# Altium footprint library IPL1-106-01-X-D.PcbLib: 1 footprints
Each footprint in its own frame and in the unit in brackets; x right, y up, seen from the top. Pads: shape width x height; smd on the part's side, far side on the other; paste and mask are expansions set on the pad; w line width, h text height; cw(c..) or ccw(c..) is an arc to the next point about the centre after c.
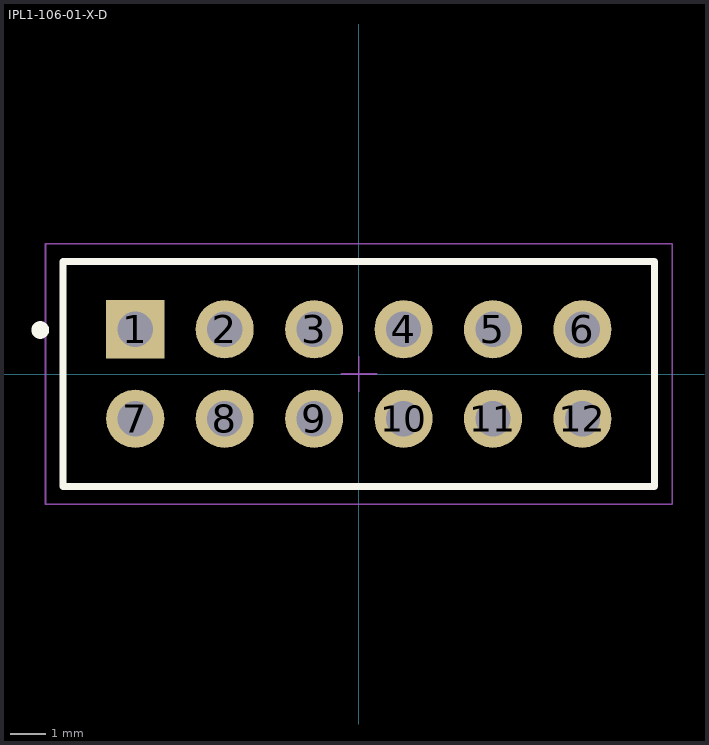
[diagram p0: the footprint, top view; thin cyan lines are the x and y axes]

## IPL1-106-01-X-D [mm] "2.54mm pitch, 12 pin, isolated power locking header"
height 8.13
pads (12):
  rect 1.65x1.65 / inner round 1.65 / far side rect 1.65x1.65 hole 1 mask+0: 1(-6.35,1.27)
  round 1.65 hole 1 mask+0: 2(-3.81,1.27) 3(-1.27,1.27) 4(1.27,1.27) 5(3.81,1.27) 6(6.35,1.27) 7(-6.35,-1.27) 8(-3.81,-1.27) 9(-1.27,-1.27) 10(1.27,-1.27) 11(3.81,-1.27) 12(6.35,-1.27)
Top Overlay:
  circle w0.25: c-9.05,1.25 r0.125
  lines w0.2: -8.4,-3.2 8.4,-3.2 8.4,3.2 -8.4,3.2 -8.4,-3.2
Mechanical 13:
  lines w0.1: -8.4,-3.2 8.4,-3.2 8.4,3.2 -8.4,3.2 -8.4,-3.2
  text ".Designator" at 0.254,0.254 h1.52
Mechanical 15:
  lines w0.05: -0.5,0 0.5,0 ; 0,-0.5 0,0.5 ; -8.9,-3.7 8.9,-3.7 8.9,3.7 -8.9,3.7 -8.9,-3.7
